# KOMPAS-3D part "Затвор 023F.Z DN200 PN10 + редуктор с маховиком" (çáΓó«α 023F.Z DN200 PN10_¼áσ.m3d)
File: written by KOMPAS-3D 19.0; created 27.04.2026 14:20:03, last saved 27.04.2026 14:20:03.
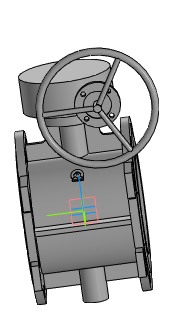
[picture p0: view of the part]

Document properties: Полное имя файла: ..\..\Затвор 023F.Z DN200-DN1600_с маховиком\Затвор 023F.Z DN200 PN10 + редуктор с маховиком.a3d

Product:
- Part/product: Затвор 023F.Z DN200 PN10 + редуктор с маховиком
    Масса: 59.9451

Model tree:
1. Операция без истории:1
